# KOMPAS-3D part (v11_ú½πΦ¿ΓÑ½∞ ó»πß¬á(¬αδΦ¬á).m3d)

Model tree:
1. Эскиз:1
2. Эскиз:2
3. Операция выдавливания:1
     Расстояние 1 = 5; Расстояние 2 = 5
4. Скругление:1
     Радиус = 1.5
5. Фаска:1
     Угол = 60; Длина 1 = 1.6; Длина 2 = 2.77128
6. Скругление:3
     Радиус = 2
7. Эскиз:3
8. Операция выдавливания:2
     Расстояние 1 = 8; Расстояние 2 = 8
9. Эскиз:4
10. Операция выдавливания:3
     Расстояние 1 = 8; Расстояние 2 = 5
11. Скругление:4
     Радиус = 1
12. Скругление:5
     Радиус = 1.4
13. Скругление:7
     Радиус = 1.4
14. Скругление:8
     Радиус = 1.4
15. Скругление:9
     Радиус = 1.4
16. Фаска:2
     Угол = 45; Длина 1 = 0.8; Длина 2 = 0.8
17. Фаска:3
     Угол = 45; Длина 1 = 0.8; Длина 2 = 0.8
18. Эскиз:5
19. Операция выдавливания:4
     Расстояние 1 = 8; Расстояние 2 = 6
20. Эскиз:6
21. Вырезать элемент выдавливания:1
     Расстояние 2 = 2; Расстояние 1 = 6

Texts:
  Линия-выноска #1
  Линия-выноска #2
  Линия-выноска #3
  Отклонения формы и база
  Марка координационной оси
  Марка/позиционное обозначение с линией-выноской
  Марка/позиционное обозначение на линии
  Марка/позиционное обозначение без линии-выноски
  Текст на чертеже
